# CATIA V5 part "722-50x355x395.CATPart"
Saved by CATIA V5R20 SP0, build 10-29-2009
Part number: 722-50x355x395
Definition: NONE
Nomenclature: 722-50x355x395
Source: Unknown
Description: 722-50x355x395
Bounding box of the stored display mesh (mm): x -25 to 25, y -24.818 to 24.818, z -337 to 58
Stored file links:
  C:\Users\Utente\Desktop\IO LAVORO\3D X SITO CF\X SITO\722\722-50x355x395.CATPart
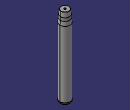
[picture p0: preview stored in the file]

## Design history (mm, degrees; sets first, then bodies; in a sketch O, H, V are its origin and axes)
Body1 "722-50x355x395" (main body)
  Solid1: solid without history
